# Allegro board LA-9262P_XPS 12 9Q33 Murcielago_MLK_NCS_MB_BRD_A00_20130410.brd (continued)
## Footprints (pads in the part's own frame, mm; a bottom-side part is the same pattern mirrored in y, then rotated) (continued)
KC_FBMA-L11-160808-800LMT_2P
  rect 0.889x1.092 smd: 1(0,0) 2(1.5,0)
KC_FBMA-L11-201209-221LMA30_2P
  rect 0.838x1.397 smd: 1(0,0) 2(1.65,0)
L3GD20TR_LGA16_4X4
  oval 0.406x0.686 smd: 1(0,0) 2(0.65,0) 3(1.3,0) 4(1.95,0) 9(1.95,3.6) 10(1.3,3.6) 11(0.65,3.6) 12(0,3.6)
  oval 0.686x0.406 smd: 5(2.775,0.825) 6(2.775,1.475) 7(2.775,2.125) 8(2.775,2.775) 13(-0.825,2.775) 14(-0.825,2.125) 15(-0.825,1.475) 16(-0.825,0.825)
L_1812-1806
  oval 1.016x3.708 smd: 1(0,0) 2(4.013,0)
LED_27-11-T1D-CP1Q1RY-3C_2P
  rect 0.991x0.991 smd: 1(0,0) 2(1.9,0)
LOTES_APCI0019-P001A01_67P-T
  round 1.092 hole 1.092 unplated: (-0.75,-5.275)
  round 1.6 hole 1.6 unplated: (19.25,-5.275)
  oval 0.305x1.549 smd: 1(0,0) 2(0.25,-7.55) 3(0.5,0) 4(0.75,-7.55) 5(1,0) 6(1.25,-7.55) 7(1.5,0) 8(1.75,-7.55) 9(2,0) 10(2.25,-7.55) 11(2.5,0) 12(2.75,-7.55) 13(3,0) 14(3.25,-7.55) 15(3.5,0) 16(3.75,-7.55) 17(4,0) 18(4.25,-7.55) 19(4.5,0) 20(4.75,-7.55) 21(5,0) 22(5.25,-7.55) 23(5.5,0) 24(7.75,-7.55) 25(8,0) 26(8.25,-7.55) 27(8.5,0) 28(8.75,-7.55) 29(9,0) 30(9.25,-7.55) 31(9.5,0) 32(9.75,-7.55) 33(10,0) 34(10.25,-7.55) 35(10.5,0) 36(10.75,-7.55) 37(11,0) 38(11.25,-7.55) 39(11.5,0) 40(11.75,-7.55) 41(12,0) 42(12.25,-7.55) 43(12.5,0) 44(12.75,-7.55) 45(13,0) 46(13.25,-7.55) 47(13.5,0) 48(13.75,-7.55) 49(14,0) 50(14.25,-7.55) 51(14.5,0) 52(14.75,-7.55) 53(15,0) 54(15.25,-7.55) 55(15.5,0) 56(15.75,-7.55) 57(16,0) 58(16.25,-7.55) 59(16.5,0) 60(16.75,-7.55) 61(17,0) 62(17.25,-7.55) 63(17.5,0) 64(17.75,-7.55) 65(18,0) 66(18.25,-7.55) 67(18.5,0)
  rect 1.194x2.743 smd: 68(-1.1,-0.775) 69(19.6,-0.775)
LPS331APTR_HCLGA16_3X3
  oval 0.305x0.66 smd: 1(0,0) 2(0.5,0) 3(1,0) 4(1.5,0) 5(2,0) 9(2,2.65) 10(1.5,2.65) 11(1,2.65) 12(0.5,2.65) 13(0,2.65)
  oval 0.66x0.305 smd: 6(2.325,0.825) 7(2.325,1.325) 8(2.325,1.825) 14(-0.325,1.825) 15(-0.325,1.325) 16(-0.325,0.825)
LSM303DLHCTR_LGA14_3X5
  oval 0.61x1.092 smd: 1(0,0) 2(0.8,0) 3(1.6,0) 4(2.4,0) 5(3.2,0) 6(4,0) 8(4,2.2) 9(3.2,2.2) 10(2.4,2.2) 11(1.6,2.2) 12(0.8,2.2) 13(0,2.2)
  oval 1.092x0.61 smd: 7(4.1,1.1) 14(-0.1,1.1)
MMBT3904_SOT23-3
  oval 1.016x1.524 smd: 1(0,0) 2(0.965,2.083) 3(-0.965,2.083)
MT41J256M16RE-15E-D_FBGA_96P
  round 0.343 smd: A1(0,0) A2(0.8,0) A3(1.6,0) A7(4.8,0) A8(5.6,0) A9(6.4,0) B1(0,-0.8) B2(0.8,-0.8) B3(1.6,-0.8) B7(4.8,-0.8) B8(5.6,-0.8) B9(6.4,-0.8) C1(0,-1.6) C2(0.8,-1.6) C3(1.6,-1.6) C7(4.8,-1.6) C8(5.6,-1.6) C9(6.4,-1.6) D1(0,-2.4) D2(0.8,-2.4) D3(1.6,-2.4) D7(4.8,-2.4) D8(5.6,-2.4) D9(6.4,-2.4) E1(0,-3.2) E2(0.8,-3.2) E3(1.6,-3.2) E7(4.8,-3.2) E8(5.6,-3.2) E9(6.4,-3.2) F1(0,-4) F2(0.8,-4) F3(1.6,-4) F7(4.8,-4) F8(5.6,-4) F9(6.4,-4) G1(0,-4.8) G2(0.8,-4.8) G3(1.6,-4.8) G7(4.8,-4.8) G8(5.6,-4.8) G9(6.4,-4.8) H1(0,-5.6) H2(0.8,-5.6) H3(1.6,-5.6) H7(4.8,-5.6) H8(5.6,-5.6) H9(6.4,-5.6) J1(0,-6.4) J2(0.8,-6.4) J3(1.6,-6.4) J7(4.8,-6.4) J8(5.6,-6.4) J9(6.4,-6.4) K1(0,-7.2) K2(0.8,-7.2) K3(1.6,-7.2) K7(4.8,-7.2) K8(5.6,-7.2) K9(6.4,-7.2) L1(0,-8) L2(0.8,-8) L3(1.6,-8) L7(4.8,-8) L8(5.6,-8) L9(6.4,-8) M1(0,-8.8) M2(0.8,-8.8) M3(1.6,-8.8) M7(4.8,-8.8) M8(5.6,-8.8) M9(6.4,-8.8) N1(0,-9.6) N2(0.8,-9.6) N3(1.6,-9.6) N7(4.8,-9.6) N8(5.6,-9.6) N9(6.4,-9.6) P1(0,-10.4) P2(0.8,-10.4) P3(1.6,-10.4) P7(4.8,-10.4) P8(5.6,-10.4) P9(6.4,-10.4) R1(0,-11.2) R2(0.8,-11.2) R3(1.6,-11.2) R7(4.8,-11.2) R8(5.6,-11.2) R9(6.4,-11.2) T1(0,-12) T2(0.8,-12) T3(1.6,-12) T7(4.8,-12) T8(5.6,-12) T9(6.4,-12)
MURAT_BLM18BD102SN1D_L0603_2P
  rect 0.66x1.041 smd: 1(0,0) 2(1.2,0)
MURAT_BLM18SG700TN1D_2P
  rect 0.66x1.041 smd: 1(0,0) 2(1.2,0)
MURAT_DLW21SN670HQ2L_4P
  rect 0.889x0.406 smd: 1(0,0) 2(1.7,0) 3(1.7,0.8) 4(0,0.8)
MURAT_LQM2MPN2R2NG0L_2P
  rect 0.787x1.803 smd: 1(0,0) 2(1.6,0)
NC7SZ175P6X_SC70-6
  oval 0.406x0.508 smd: 1(0,0) 2(0.65,0) 3(1.3,0) 4(1.3,1.9) 5(0.65,1.9) 6(0,1.9)
NCP4545IMNTWG_QFN18_3X3
  oval 0.254x0.94 smd: 1(0,0) 2(0.5,0) 3(1,0) 4(1.5,0) 10(1.5,3.05) 11(1,3.05) 12(0.5,3.05) 13(0,3.05)
  oval 0.94x0.254 smd: 5(2.275,0.525) 6(2.275,1.025) 7(2.275,1.525) 8(2.275,2.025) 9(2.275,2.525) 14(-0.775,2.525) 15(-0.775,2.025) 16(-0.775,1.525) 17(-0.775,1.025) 18(-0.775,0.525)
  rect 1.854x1.854 smd: 19(0.75,1.525)
PESD5V0U2BT_SOT23-3
  oval 1.016x1.524 smd: 1(0,0) 2(0.965,2.083) 3(-0.965,2.083)
R0402_0OHM
  rect 0.508x0.559 smd: 1(0,0) 2(0.914,0)
R0603_0OHM
  rect 0.635x0.889 smd: 1(0,0) 2(1.397,0)
R0805_0OHM
  rect 0.813x1.397 smd: 1(0,0) 2(1.702,0)
R_0402
  rect 0.508x0.559 smd: 1(0,0) 2(0.914,0)
R_0603
  rect 0.635x0.889 smd: 1(0,0) 2(1.397,0)
R_0805
  rect 0.813x1.397 smd: 1(0,0) 2(1.702,0)
R_1206
  rect 1.016x1.651 smd: 1(0,0) 2(2.667,0)
R_1206_4P-D
  custom 0.445x0.445 smd: 1(0,0) 4(5.004,0)
  custom 0.114x0.114 smd: 2(1.194,0) 3(3.81,0)
RB751V-40_SOD323-2
  rect 0.787x0.889 smd: 1(0,0) 2(2.14,0)
RB751V-40GTE-17_SOD323-2
  rect 0.787x0.889 smd: 1(0,0) 2(2.1,0)
RB751V-40TE17_SOD323-2
  rect 0.787x0.889 smd: 1(0,0) 2(0,-2.1)
RCLAMP0524PATCT_SLP2510P8-10-9
  oval 0.203x0.686 smd: 1(0,0) 2(0.5,0) 4(1.5,0) 5(2,0) 6(2,0.875) 7(1.5,0.875) 8(0.5,0.875) 9(0,0.875)
  oval 0.406x1.549 smd: 3(1,0.437)
RHU002N06_SOT323-3
  oval 0.813x0.914 smd: 1(0,0) 2(0.65,1.6) 3(-0.65,1.6)
RP_0804_8P4R
  oval 0.66x0.254 smd: 1(0,0) 2(0,-0.5) 3(0,-1) 4(0,-1.5) 5(1.15,-1.5) 6(1.15,-1) 7(1.15,-0.5) 8(1.15,0)
RT8207MZQW_WQFN20_3X3
  oval 0.203x0.889 smd: 1(0,0) 2(0.4,0) 3(0.8,0) 4(1.2,0) 5(1.6,0) 11(1.6,3.1) 12(1.2,3.1) 13(0.8,3.1) 14(0.4,3.1) 15(0,3.1)
  oval 0.889x0.203 smd: 6(2.35,0.75) 7(2.35,1.15) 8(2.35,1.55) 9(2.35,1.95) 10(2.35,2.35) 16(-0.75,2.35) 17(-0.75,1.95) 18(-0.75,1.55) 19(-0.75,1.15) 20(-0.75,0.75)
  rect 1.702x1.702 smd: 21(0.8,1.55)
SAMTE_BSH-030-01-L-D-A_60P
  round 1.016 hole 1.016 unplated: (-2.81,5.53) (17.316,5.53)
  oval 0.279x2.261 smd: 1(0,0) 2(0,5.728) 3(0.5,0) 4(0.5,5.728) 5(1,0) 6(1,5.728) 7(1.5,0) 8(1.5,5.728) 9(2,0) 10(2,5.728) 11(2.5,0) 12(2.5,5.728) 13(3,0) 14(3,5.728) 15(3.5,0) 16(3.5,5.728) 17(4,0) 18(4,5.728) 19(4.5,0) 20(4.5,5.728) 21(5,0) 22(5,5.728) 23(5.5,0) 24(5.5,5.728) 25(6,0) 26(6,5.728) 27(6.5,0) 28(6.5,5.728) 29(7,0) 30(7,5.728) 31(7.5,0) 32(7.5,5.728) 33(8,0) 34(8,5.728) 35(8.5,0) 36(8.5,5.728) 37(9,0) 38(9,5.728) 39(9.5,0) 40(9.5,5.728) 41(10,0) 42(10,5.728) 43(10.5,0) 44(10.5,5.728) 45(11,0) 46(11,5.728) 47(11.5,0) 48(11.5,5.728) 49(12,0) 50(12,5.728) 51(12.5,0) 52(12.5,5.728) 53(13,0) 54(13,5.728) 55(13.5,0) 56(13.5,5.728) 57(14,0) 58(14,5.728) 59(14.5,0) 60(14.5,5.728)
SDMK0340L-7-F_SOD323-2
  rect 1.346x0.66 smd: 1(0,0) 2(2.4,0)
SHARK-BAY-ULT_BGA_1168P-T
  round 0.508 smd: A3(-1.137,0) A62(-38.036,0) AW1(0,22.042) AW63(-38.628,22.057) AY2(-0.543,22.628) AY62(-38.062,22.628) B2(-0.508,0.508) B63(-38.628,0.592) C1(0,1.137)
  round 0.381 smd: A4(-1.894,0) A5(-2.554,0) A6(-3.75,0) A59(-35.9,0) A60(-36.726,0) A61(-37.386,0) AA9(-5.032,11.576) AA21(-11.688,11.489) AA23(-13.115,11.489) AA58(-35.377,11.33) AB10(-5.476,12.053) AB20(-11.18,11.896) AB21(-11.688,12.302) AB22(-12.607,11.896) AB23(-13.115,12.302) AB57(-35.057,11.98) AC9(-5.032,12.529) AC20(-11.18,12.709) AC22(-12.607,12.709) AC58(-35.377,12.63) AD10(-5.476,13.005) AD21(-11.688,13.115) AD23(-13.115,13.115) AD57(-35.057,13.28) AE9(-5.032,13.481) AE10(-5.476,13.958) AE20(-11.18,13.521) AE21(-11.688,13.928) AE22(-12.607,13.521) AE23(-13.115,13.928) AE58(-35.377,13.931) AF9(-5.032,14.434) AF11(-6.059,14.282) AF12(-6.872,14.282) AF14(-7.685,14.282) AF15(-8.497,14.282) AF17(-9.31,14.282) AF18(-10.123,14.282) AF20(-10.936,14.282) AF22(-12.607,14.334) AG10(-5.653,14.79) AG11(-6.465,14.79) AG13(-7.278,14.79) AG14(-8.091,14.79) AG16(-8.904,14.79) AG17(-9.717,14.79) AG19(-10.529,14.79) AG20(-11.342,14.79) AG23(-13.115,14.741) AG57(-35.057,14.581) AG58(-35.692,15.009) AH22(-12.607,15.147) AH24(-13.92,15.289) AH26(-15.22,15.289) AH28(-16.521,15.289) AH30(-17.821,15.289) AH32(-19.122,15.289) AH34(-20.422,15.289) AH36(-21.723,15.289) AH38(-23.023,15.289) AH40(-24.324,15.289) AH42(-25.624,15.289) AH44(-26.925,15.289) AH46(-28.225,15.289) AH49(-29.526,15.289) AH51(-30.826,15.289) AH53(-32.127,15.289) AH55(-33.427,15.289) AH57(-34.728,15.289) AJ23(-13.115,15.553) AJ25(-14.57,15.614) AJ27(-15.871,15.614) AJ29(-17.171,15.614) AJ31(-18.472,15.614) AJ33(-19.772,15.614) AJ35(-21.073,15.614) AJ37(-22.373,15.614) AJ39(-23.674,15.614) AJ41(-24.974,15.614) AJ43(-26.275,15.614) AJ45(-27.575,15.614) AJ47(-28.875,15.614) AJ50(-30.176,15.614) AJ52(-31.476,15.614) AJ54(-32.777,15.614) AJ56(-34.077,15.614) AJ58(-35.378,15.614) AT1(0,19.997) AT63(-38.628,19.848) AU1(0,20.657) AU63(-38.628,20.673) AV1(0,21.318) AV2(-0.66,21.308) AV62(-37.978,21.318) AV63(-38.628,21.333) AW2(-0.66,21.968) AW3(-1.321,21.968) AW61(-37.328,21.978) AW62(-37.978,21.978) AY3(-1.267,22.628) AY4(-1.928,22.628) AY5(-2.588,22.628) AY59(-36.088,22.628) AY60(-36.748,22.628) AY61(-37.409,22.628) B3(-1.259,0.65) B61(-37.315,0.66) B62(-37.978,0.724) C2(-0.65,1.259) C62(-37.978,1.384) C63(-38.628,1.316) D1(0,1.861) D63(-38.628,1.976) E1(0,2.522) E23(-13.333,2.601) E25(-14.714,2.601) E27(-15.84,2.601) E29(-17.221,2.601) E31(-18.348,2.601) E33(-19.729,2.601) E35(-20.855,2.601) E37(-22.236,2.601) E39(-23.363,2.601) E41(-24.744,2.601) E43(-25.87,2.601) E45(-27.251,2.601) E47(-28.378,2.601) E49(-29.759,2.601) E51(-30.885,2.601) E53(-32.266,2.601) E55(-33.393,2.601) E57(-34.774,2.601) E63(-38.628,2.647) F1(0,3.436) F22(-12.717,3.058) F24(-14.023,3.126) F26(-15.277,3.126) F28(-16.531,3.126) F30(-17.785,3.126) F32(-19.038,3.126) F34(-20.292,3.126) F36(-21.546,3.126) F38(-22.8,3.126) F40(-24.053,3.126) F42(-25.307,3.126) F44(-26.561,3.126) F46(-27.815,3.126) F48(-29.068,3.126) F50(-30.322,3.126) F52(-31.576,3.126) F54(-32.83,3.126) F56(-34.083,3.126) F58(-35.377,3.126) G22(-12.607,3.768) G23(-13.333,3.451) G25(-14.714,3.451) G27(-15.84,3.451) G29(-17.221,3.451) G31(-18.348,3.451) G33(-19.729,3.451) G35(-20.855,3.451) G37(-22.236,3.451) G39(-23.363,3.451) G41(-24.744,3.451) G43(-25.87,3.451) G45(-27.251,3.451) G47(-28.378,3.451) G49(-29.759,3.451) G51(-30.885,3.451) G53(-32.266,3.451) G55(-33.393,3.451) G57(-34.774,3.451) H22(-12.607,4.581) H23(-13.115,4.174) H57(-35.057,4.101) J22(-12.607,5.393) J23(-13.115,4.987) J58(-35.377,4.827) K9(-5.032,5.861) K10(-5.935,5.7) K12(-6.888,5.7) K14(-7.84,5.7) K16(-8.793,5.7) K18(-9.745,5.7) K19(-10.698,5.7) K21(-11.65,5.7) K23(-13.115,5.8) K57(-35.057,5.478) L10(-5.476,6.338) L11(-6.412,6.144) L13(-7.364,6.144) L15(-8.317,6.144) L17(-9.269,6.144) L18(-10.222,6.144) L20(-11.18,6.206) L22(-12.607,6.206) L58(-35.377,6.128) M9(-5.032,6.814) M20(-11.18,7.019) M21(-11.688,6.613) M22(-12.607,7.019) M23(-13.115,6.613) M57(-35.057,6.778) N10(-5.476,7.29) N21(-11.688,7.425) N23(-13.115,7.425) N58(-35.377,7.428) P9(-5.032,7.766) P20(-11.18,7.832) P22(-12.607,7.832) P57(-35.057,8.078) R10(-5.476,8.243) R20(-11.18,8.645) R21(-11.688,8.238) R22(-12.607,8.645) R23(-13.115,8.238) T9(-5.032,8.719) T21(-11.688,9.051) T23(-13.115,9.051) T58(-35.377,8.729) U9(-5.032,9.671) U10(-5.476,9.195) U20(-11.18,9.457) U22(-12.607,9.457) U57(-35.057,9.379) V10(-5.476,10.148) V21(-11.688,9.864) V23(-13.115,9.864) V58(-35.377,10.029) W9(-5.032,10.624) W20(-11.18,10.27) W21(-11.688,10.677) W22(-12.607,10.27) W23(-13.115,10.677) W57(-35.057,10.679) Y10(-5.476,11.1) Y20(-11.18,11.083) Y22(-12.607,11.083)
  round 0.305 smd: A8(-4.538,0) A9(-5.452,0) A11(-6.367,0) A12(-7.116,0) A14(-8.03,0) A15(-8.945,0) A17(-9.694,0) A18(-10.608,0) A20(-11.523,0) A21(-12.272,0) A23(-13.186,0) A24(-14.023,0.325) A25(-14.714,0) A27(-15.84,0) A28(-16.531,0.325) A29(-17.221,0) A31(-18.348,0) A32(-19.038,0.325) A33(-19.729,0) A35(-20.855,0) A36(-21.546,0.325) A37(-22.236,0) A39(-23.363,0) A40(-24.053,0.325) A41(-24.744,0) A43(-25.87,0) A44(-26.561,0.325) A45(-27.251,0) A47(-28.378,0) A48(-29.068,0.325) A49(-29.759,0) A51(-30.885,0) A52(-31.576,0.325) A53(-32.266,0) A55(-33.393,0) A56(-34.083,0.325) A57(-34.774,0) AA1(0,11.717) AA2(-0.65,11.717) AA3(-1.3,11.678) AA4(-1.951,11.678) AA59(-36.027,11.638) AA60(-36.678,11.638) AA61(-37.328,11.638) AA62(-37.978,11.676) AA63(-38.628,11.676) AB5(-2.637,12.053) AB6(-3.287,12.053) AB7(-3.937,12.053) AB8(-4.587,12.053) AC1(0,12.466) AC2(-0.65,12.466) AC3(-1.3,12.504) AC4(-1.951,12.504) AC59(-36.027,12.464) AC60(-36.678,12.464) AC61(-37.328,12.464) AC62(-37.978,12.426) AC63(-38.628,12.426) AD1(0,13.215) AD2(-0.65,13.215) AD3(-1.3,13.177) AD4(-1.951,13.177) AD5(-2.637,13.005) AD6(-3.287,13.005) AD7(-3.937,13.005) AD8(-4.587,13.005) AD59(-36.027,13.137) AD60(-36.678,13.137) AD61(-37.328,13.137) AD62(-37.978,13.175) AD63(-38.628,13.175) AE5(-2.637,13.958) AE6(-3.287,13.958) AE7(-3.937,13.958) AE8(-4.587,13.958) AE59(-36.027,13.962) AE60(-36.678,13.962) AE61(-37.328,13.962) AE62(-37.978,13.924) AE63(-38.628,13.924) AF1(0,13.964) AF2(-0.65,13.964) AF3(-1.3,14.003) AF4(-1.951,14.003) AG1(0,14.714) AG2(-0.65,14.714) AG3(-1.3,14.676) AG4(-1.951,14.676) AG5(-2.637,14.91) AG6(-3.287,14.91) AG7(-3.937,14.91) AG8(-4.587,14.91) AG21(-11.955,15.122) AG60(-36.352,14.602) AG61(-37.003,14.602) AG62(-37.653,14.602) AG63(-38.303,14.602) AH1(0,15.463) AH2(-0.65,15.463) AH3(-1.3,15.501) AH4(-1.951,15.501) AH10(-5.653,15.476) AH11(-6.465,15.476) AH13(-7.278,15.476) AH14(-8.091,15.476) AH16(-8.904,15.476) AH17(-9.717,15.476) AH19(-10.529,15.476) AH20(-11.342,15.476) AH60(-36.678,15.278) AH61(-37.328,15.278) AH62(-37.978,15.278) AH63(-38.628,15.278) AJ5(-2.637,15.863) AJ6(-3.287,15.863) AJ7(-3.937,15.863) AJ8(-4.587,15.863) AJ10(-5.653,16.126) AJ11(-6.465,16.126) AJ13(-7.278,16.126) AJ14(-8.091,16.126) AJ60(-36.352,15.954) AJ61(-37.003,15.954) AJ62(-37.653,15.954) AJ63(-38.303,15.954) AK1(0,16.212) AK2(-0.65,16.212) AK3(-1.3,16.174) AK4(-1.951,16.174) AK8(-4.303,16.451) AK18(-9.848,16.266) AK20(-10.801,16.266) AK21(-11.753,16.266) AK60(-36.678,16.523) AK61(-37.328,16.523) AK62(-37.978,16.629) AK63(-38.628,16.629) AL1(0,16.962) AL2(-0.65,16.962) AL3(-1.3,17) AL4(-1.951,17) AL5(-2.901,16.776) AL7(-3.739,16.776) AL8(-4.303,17.101) AL10(-5.658,16.776) AL11(-6.221,17.101) AL13(-7.576,16.776) AL15(-8.14,17.101) AL17(-9.222,16.583) AL18(-9.848,16.916) AL20(-10.801,16.916) AL21(-11.753,16.916) AL22(-12.706,16.916) AL23(-13.529,16.916) AL25(-14.504,16.916) AL26(-15.456,16.916) AL28(-16.409,16.916) AL29(-17.361,16.916) AL31(-18.26,16.591) AL32(-18.824,16.916) AL33(-19.726,16.916) AL35(-20.729,16.916) AL36(-21.58,16.916) AL38(-22.634,16.916) AL39(-23.542,16.591) AL40(-24.131,16.916) AL42(-24.944,16.916) AL43(-25.897,16.916) AL45(-26.874,16.916) AL46(-27.802,16.916) AL48(-28.856,16.916) AL49(-29.757,16.916) AL51(-30.761,16.916) AL52(-31.583,16.916) AL54(-32.61,16.916) AL55(-33.562,16.916) AL57(-34.509,16.916) AL58(-35.408,16.916) AL60(-36.352,17.169) AL61(-37.003,17.169) AM1(0,17.711) AM2(-0.65,17.711) AM3(-1.3,17.673) AM4(-1.951,17.673) AM5(-2.901,17.426) AM7(-3.739,17.426) AM8(-4.303,17.752) AM10(-5.658,17.426) AM11(-6.221,17.752) AM13(-7.576,17.426) AM15(-8.14,17.752) AM17(-9.222,17.233) AM18(-9.848,17.567) AM20(-10.801,17.567) AM21(-11.753,17.567) AM22(-12.706,17.567) AM23(-13.529,17.567) AM25(-14.504,17.567) AM26(-15.456,17.567) AM28(-16.409,17.567) AM29(-17.361,17.567) AM31(-18.26,17.242) AM32(-18.824,17.567) AM33(-19.726,17.567) AM35(-20.729,17.567) AM36(-21.58,17.567) AM38(-22.634,17.567) AM40(-24.131,17.567) AM42(-24.944,17.567) AM43(-25.897,17.567) AM45(-26.874,17.567) AM46(-27.802,17.567) AM48(-28.856,17.567) AM49(-29.757,17.567) AM51(-30.761,17.567) AM52(-31.583,17.567) AM54(-32.61,17.567) AM55(-33.562,17.567) AM57(-34.509,17.567) AM58(-35.408,17.567) AM60(-36.678,17.816) AM61(-37.328,17.816) AM62(-37.978,17.709) AM63(-38.628,17.709) AN1(0,18.46) AN2(-0.65,18.46) AN3(-1.3,18.498) AN4(-1.951,18.498) AN5(-2.901,18.077) AN7(-3.739,18.077) AN8(-4.303,18.402) AN10(-5.658,18.077) AN11(-6.221,18.402) AN13(-7.576,18.077) AN15(-8.14,18.402) AN17(-9.222,17.883) AN18(-9.848,18.217) AN20(-10.801,18.217) AN21(-11.753,18.217) AN22(-12.706,18.217) AN23(-13.529,18.217) AN25(-14.504,18.217) AN26(-15.456,18.217) AN28(-16.409,18.217) AN29(-17.361,18.217) AN31(-18.26,17.892) AN32(-18.824,18.217) AN33(-19.726,18.217) AN35(-20.729,18.217) AN36(-21.58,18.217) AN38(-22.634,18.217) AN39(-23.542,17.892) AN40(-24.131,18.217) AN42(-24.944,18.217) AN43(-25.897,18.217) AN45(-26.874,18.217) AN46(-27.802,18.217) AN48(-28.856,18.217) AN49(-29.757,18.217) AN51(-30.761,18.217) AN52(-31.583,18.217) AN54(-32.61,18.217) AN55(-33.562,18.217) AN57(-34.509,18.217) AN58(-35.408,18.217) AN60(-36.352,18.385) AN61(-37.003,18.385) AN62(-37.653,18.385) AN63(-38.303,18.385) AP1(0,19.21) AP2(-0.65,19.21) AP3(-1.3,19.171) AP4(-1.951,19.171) AP5(-2.901,18.727) AP7(-3.739,18.727) AP8(-4.303,19.052) AP10(-5.658,18.727) AP11(-6.221,19.052) AP13(-7.576,18.727) AP15(-8.14,19.052) AP17(-9.222,18.533) AP18(-9.848,18.867) AP20(-10.801,18.867) AP21(-11.753,18.867) AP22(-12.706,18.867) AP23(-13.529,18.867) AP25(-14.504,18.867) AP26(-15.456,18.867) AP28(-16.409,18.867) AP29(-17.361,18.867) AP31(-18.26,18.542) AP32(-18.824,18.867) AP33(-19.726,18.867) AP35(-20.729,18.867) AP36(-21.58,18.867) AP38(-22.634,18.867) AP39(-23.542,18.542) AP40(-24.131,18.867) AP42(-24.944,18.867) AP43(-25.897,18.867) AP45(-26.874,18.867) AP46(-27.802,18.867) AP48(-28.856,18.867) AP49(-29.757,18.867) AP51(-30.761,18.867) AP52(-31.583,18.867) AP54(-32.61,18.867) AP55(-33.562,18.867) AP57(-34.509,18.867) AP58(-35.408,18.867) AP60(-36.678,19.06) AP61(-37.328,19.06) AP62(-37.978,19.06) AP63(-38.628,19.06) AR5(-2.901,19.377) AR7(-3.739,19.377) AR8(-4.303,19.702) AR10(-5.658,19.377) AR11(-6.221,19.702) AR13(-7.576,19.377) AR15(-8.14,19.702) AR17(-9.222,19.184) AR18(-9.848,19.517) AR20(-10.801,19.517) AR21(-11.753,19.517) AR22(-12.706,19.517) AR23(-13.529,19.517) AR25(-14.504,19.517) AR26(-15.456,19.517) AR28(-16.409,19.517) AR29(-17.361,19.517) AR31(-18.26,19.192) AR32(-18.824,19.517) AR33(-19.726,19.517) AR35(-20.729,19.517) AR36(-21.58,19.517) AR38(-22.634,19.517) AR39(-23.542,19.192) AR40(-24.131,19.517) AR42(-24.944,19.517) AR43(-25.897,19.517) AR45(-26.874,19.517) AR46(-27.802,19.517) AR48(-28.856,19.517) AR49(-29.757,19.517) AR51(-30.761,19.517) AR52(-31.583,19.517) AR54(-32.61,19.517) AR55(-33.562,19.517) AR57(-34.509,19.517) AR58(-35.408,19.517) AT2(-0.65,19.959) AT3(-1.3,19.997) AT4(-1.951,19.997) AT5(-2.901,20.027) AT7(-3.739,20.027) AT10(-5.658,20.027) AT13(-7.576,20.027) AT35(-20.437,20.22) AT37(-22.011,20.22) AT40(-23.586,20.22) AT42(-25.161,20.22) AT43(-26.736,20.22) AT46(-28.311,20.22) AT49(-29.912,20.248) AT61(-37.003,19.634) AT62(-37.812,19.69) AU2(-0.655,20.647) AU3(-1.315,20.647) AU4(-1.976,20.647) AU6(-3.337,20.678) AU7(-4.163,20.678) AU8(-4.836,20.678) AU10(-5.661,20.678) AU11(-6.335,20.678) AU12(-7.16,20.678) AU14(-7.833,20.678) AU15(-8.659,20.678) AU16(-9.222,20.353) AU17(-9.86,20.678) AU18(-10.536,20.353) AU19(-11.105,20.678) AU20(-11.751,20.353) AU21(-12.397,20.678) AU22(-12.966,20.353) AU23(-13.642,20.678) AU24(-14.318,20.353) AU25(-14.993,20.678) AU26(-15.669,20.353) AU27(-16.238,20.678) AU28(-16.884,20.353) AU29(-17.531,20.678) AU30(-18.1,20.353) AU31(-18.775,20.678) AU33(-19.372,20.33) AU34(-19.974,20.678) AU35(-20.899,20.678) AU36(-21.549,20.678) AU37(-22.474,20.678) AU39(-23.124,20.678) AU40(-24.048,20.678) AU41(-24.699,20.678) AU42(-25.623,20.678) AU43(-26.274,20.678) AU44(-27.198,20.678) AU46(-27.848,20.678) AU47(-28.773,20.678) AU49(-29.423,20.678) AU50(-30.4,20.678) AU51(-30.98,20.353) AU52(-31.656,20.678) AU53(-32.331,20.353) AU54(-32.9,20.678) AU55(-33.547,20.353) AU56(-34.193,20.678) AU57(-34.762,20.353) AU58(-35.438,20.678) AU59(-36.002,20.353) AU60(-36.566,20.678) AU61(-37.277,20.401) AU62(-37.978,20.663) AV3(-1.321,21.308) AV4(-1.976,21.308) AV5(-2.664,21.328) AV6(-3.337,21.328) AV7(-4.163,21.328) AV8(-4.836,21.328) AV10(-5.661,21.328) AV11(-6.335,21.328) AV12(-7.16,21.328) AV14(-7.833,21.328) AV15(-8.659,21.328) AV16(-9.222,21.003) AV17(-9.86,21.328) AV18(-10.536,21.003) AV19(-11.105,21.328) AV20(-11.751,21.003) AV21(-12.397,21.328) AV22(-12.966,21.003) AV23(-13.642,21.328) AV24(-14.318,21.003) AV25(-14.993,21.328) AV26(-15.669,21.003) AV27(-16.238,21.328) AV28(-16.884,21.003) AV29(-17.531,21.328) AV30(-18.1,21.003) AV31(-18.775,21.328) AV33(-19.4,21.003) AV34(-20.024,21.328) AV35(-20.849,21.328) AV36(-21.599,21.328) AV37(-22.424,21.328) AV39(-23.173,21.328) AV40(-23.999,21.328) AV41(-24.748,21.328) AV42(-25.574,21.328) AV43(-26.323,21.328) AV44(-27.149,21.328) AV46(-27.898,21.328) AV47(-28.723,21.328) AV49(-29.473,21.328) AV50(-30.298,21.328) AV51(-30.98,21.003) AV52(-31.656,21.328) AV53(-32.331,21.003) AV54(-32.9,21.328) AV55(-33.547,21.003) AV56(-34.193,21.328) AV57(-34.762,21.003) AV58(-35.438,21.328) AV59(-36.002,21.003) AV60(-36.566,21.328) AV61(-37.302,21.051) AW4(-1.976,21.968) AW5(-2.626,21.978) AW6(-3.375,21.978) AW7(-4.125,21.978) AW8(-4.874,21.978) AW10(-5.623,21.978) AW11(-6.373,21.978) AW12(-7.122,21.978) AW14(-7.871,21.978) AW15(-8.621,21.978) AW16(-9.222,21.653) AW17(-9.86,21.978) AW18(-10.536,21.653) AW19(-11.211,21.978) AW21(-12.291,21.978) AW22(-12.966,21.653) AW23(-13.642,21.978) AW24(-14.318,21.653) AW25(-14.993,21.978) AW26(-15.669,21.653) AW27(-16.345,21.978) AW29(-17.424,21.978) AW30(-18.1,21.653) AW31(-18.775,21.978) AW33(-19.451,21.653) AW34(-20.024,21.978) AW35(-20.849,21.978) AW36(-21.599,21.978) AW37(-22.424,21.978) AW39(-23.173,21.978) AW40(-23.999,21.978) AW41(-24.748,21.978) AW42(-25.574,21.978) AW43(-26.323,21.978) AW44(-27.149,21.978) AW46(-27.898,21.978) AW47(-28.723,21.978) AW49(-29.473,21.978) AW50(-30.298,21.978) AW51(-30.98,21.653) AW52(-31.656,21.978) AW53(-32.331,21.653) AW54(-33.007,21.978) AW56(-34.087,21.978) AW57(-34.762,21.653) AW58(-35.438,21.978) AW59(-36.002,21.653) AW60(-36.566,21.978) AY6(-3.375,22.628) AY7(-4.125,22.628) AY8(-4.874,22.628) AY10(-5.623,22.628) AY11(-6.373,22.628) AY12(-7.122,22.628) AY14(-7.871,22.628) AY15(-8.621,22.628) AY16(-9.184,22.303) AY17(-9.86,22.628) AY18(-10.536,22.303) AY19(-11.211,22.628) AY21(-12.291,22.628) AY22(-12.966,22.303) AY23(-13.642,22.628) AY24(-14.318,22.303) AY25(-14.993,22.628) AY26(-15.669,22.303) AY27(-16.345,22.628) AY29(-17.424,22.628) AY30(-18.1,22.303) AY31(-18.775,22.628) AY33(-19.451,22.303) AY34(-20.024,22.628) AY35(-20.849,22.628) AY36(-21.599,22.628) AY37(-22.424,22.628) AY39(-23.173,22.628) AY40(-23.999,22.628) AY41(-24.748,22.628) AY42(-25.574,22.628) AY43(-26.323,22.628) AY44(-27.149,22.628) AY46(-27.898,22.628) AY47(-28.723,22.628) AY49(-29.473,22.628) AY50(-30.298,22.628) AY51(-30.98,22.303) AY52(-31.656,22.628) AY53(-32.331,22.303) AY54(-33.007,22.628) AY56(-34.087,22.628) AY57(-34.762,22.303) AY58(-35.438,22.628) B4(-1.922,0.65) B5(-3.138,0.643) B6(-4.119,0.643) B8(-4.891,0.643) B9(-5.716,0.643) B11(-6.697,0.643) B12(-7.469,0.643) B14(-8.294,0.643) B15(-9.275,0.643) B17(-10.047,0.643) B18(-10.872,0.643) B20(-11.853,0.643) B21(-12.272,1.196) B22(-12.625,0.643) B23(-13.451,0.643) B24(-14.023,0.975) B25(-14.714,0.65) B26(-15.277,0.975) B27(-15.84,0.65) B28(-16.531,0.975) B29(-17.221,0.65) B30(-17.785,0.975) B31(-18.348,0.65) B32(-19.038,0.975) B33(-19.729,0.65) B34(-20.292,0.975) B35(-20.855,0.65) B36(-21.546,0.975) B37(-22.236,0.65) B38(-22.8,0.975) B39(-23.363,0.65) B40(-24.053,0.975) B41(-24.744,0.65) B42(-25.307,0.975) B43(-25.87,0.65) B44(-26.561,0.975) B45(-27.251,0.65) B46(-27.815,0.975) B47(-28.378,0.65) B48(-29.068,0.975) B49(-29.759,0.65) B50(-30.322,0.975) B51(-30.885,0.65) B52(-31.576,0.975) B53(-32.266,0.65) B54(-32.83,0.975) B55(-33.393,0.65) B56(-34.083,0.975) B57(-34.774,0.65) B58(-35.337,0.975) B59(-35.9,0.65) B60(-36.665,0.66) C3(-1.302,1.302) C4(-2.118,1.272) C5(-2.772,1.196) C6(-3.776,1.196) C8(-4.538,1.196) C9(-5.351,1.196) C11(-6.354,1.196) C12(-7.116,1.196) C14(-7.929,1.196) C15(-8.932,1.196) C17(-9.694,1.196) C18(-10.507,1.196) C20(-11.51,1.196) C21(-11.891,1.786) C22(-12.678,1.786) C23(-13.085,1.196) C24(-14.051,2.032) C25(-14.714,1.3) C26(-15.277,1.626) C27(-15.84,1.3) C28(-16.558,2.032) C29(-17.221,1.3) C30(-17.785,1.626) C31(-18.348,1.3) C32(-19.066,2.032) C33(-19.729,1.3) C34(-20.292,1.626) C35(-20.855,1.3) C36(-21.573,2.032) C37(-22.236,1.3) C38(-22.8,1.626) C39(-23.363,1.3) C40(-24.081,2.032) C41(-24.744,1.3) C42(-25.307,1.626) C43(-25.87,1.3) C44(-26.588,2.032) C45(-27.251,1.3) C46(-27.815,1.626) C47(-28.378,1.3) C48(-29.07,2.032) C49(-29.759,1.3) C50(-30.322,1.626) C51(-30.885,1.3) C52(-31.578,1.991) C53(-32.266,1.3) C54(-32.83,1.626) C55(-33.393,1.3) C56(-34.085,1.991) C57(-34.774,1.3) C58(-35.337,1.626) C59(-35.9,1.3) C61(-37.003,1.237) D2(-0.65,2.075) D3(-1.3,2.037) D5(-2.678,1.842) D6(-3.369,1.786) D8(-4.157,1.786) D9(-4.944,1.786) D11(-5.852,1.786) D12(-6.735,1.786) D14(-7.522,1.786) D15(-8.43,1.786) D17(-9.313,1.786) D18(-10.1,1.786) D20(-11.008,1.786) D21(-12.235,2.423) D23(-13.377,1.786) D25(-14.714,1.951) D26(-15.277,2.276) D27(-15.84,1.951) D29(-17.221,1.951) D30(-17.785,2.276) D31(-18.348,1.951) D33(-19.729,1.951) D34(-20.292,2.276) D35(-20.855,1.951) D37(-22.236,1.951) D38(-22.8,2.276) D39(-23.363,1.951) D41(-24.744,1.951) D42(-25.307,2.276) D43(-25.87,1.951) D45(-27.251,1.951) D46(-27.815,2.276) D47(-28.378,1.951) D49(-29.759,1.951) D50(-30.322,2.276) D51(-30.885,1.951) D53(-32.266,1.951) D54(-32.83,2.276) D55(-33.393,1.951) D57(-34.774,1.951) D58(-35.337,2.276) D59(-35.9,1.951) D60(-36.678,1.801) D61(-37.328,1.801) D62(-37.978,2.035) E2(-0.65,2.725) E3(-1.3,2.687) E4(-1.951,2.687) E5(-2.602,2.619) E6(-3.554,2.619) E8(-4.507,2.619) E10(-5.459,2.619) E11(-6.412,2.619) E13(-7.364,2.619) E15(-8.317,2.619) E17(-9.269,2.619) E18(-10.222,2.619) E20(-11.174,2.619) E59(-36.027,2.647) E60(-36.678,2.647) E61(-37.328,2.647) E62(-37.978,2.685) F2(-0.65,3.474) F3(-1.3,3.512) F4(-1.951,3.512) F5(-2.602,3.269) F6(-3.554,3.269) F8(-4.507,3.269) F10(-5.459,3.269) F11(-6.412,3.269) F13(-7.364,3.269) F15(-8.317,3.269) F17(-9.269,3.269) F18(-10.222,3.269) F20(-11.174,3.269) F59(-36.027,3.472) F60(-36.678,3.472) F61(-37.328,3.472) F62(-37.978,3.434) F63(-38.628,3.434) G1(0,4.224) G2(-0.65,4.224) G3(-1.3,4.185) G4(-1.951,4.185) G5(-2.602,3.919) G6(-3.554,3.919) G8(-4.507,3.919) G10(-5.459,3.919) G11(-6.412,3.919) G13(-7.364,3.919) G15(-8.317,3.919) G17(-9.269,3.919) G18(-10.222,3.919) G20(-11.174,3.919) H5(-2.602,4.569) H6(-3.554,4.569) H8(-4.507,4.569) H10(-5.459,4.569) H11(-6.412,4.569) H13(-7.364,4.569) H15(-8.317,4.569) H17(-9.269,4.569) H18(-10.222,4.569) H20(-11.174,4.569) H59(-36.027,4.145) H60(-36.678,4.145) H61(-37.328,4.145) H62(-37.978,4.183) H63(-38.628,4.183) J1(0,4.973) J2(-0.65,4.973) J3(-1.3,5.011) J4(-1.951,5.011) J5(-2.627,5.22) J6(-3.567,5.22) J8(-4.507,5.22) J10(-5.459,5.22) J11(-6.412,5.22) J13(-7.364,5.22) J15(-8.317,5.22) J17(-9.269,5.22) J18(-10.222,5.22) J20(-11.174,5.22) J21(-12.095,4.986) J59(-36.027,4.971) J60(-36.678,4.971) J61(-37.328,4.971) J62(-37.978,4.933) J63(-38.628,4.933) K1(0,5.722) K2(-0.65,5.722) K3(-1.3,5.684) K4(-1.951,5.684) K59(-36.027,5.644) K60(-36.678,5.644) K61(-37.328,5.644) K62(-37.978,5.682) K63(-38.628,5.682) L1(0,6.471) L2(-0.65,6.471) L3(-1.3,6.51) L4(-1.951,6.51) L5(-2.637,6.338) L6(-3.287,6.338) L7(-3.937,6.338) L8(-4.587,6.338) L59(-36.027,6.469) L60(-36.678,6.469) L61(-37.328,6.469) L62(-37.978,6.431) L63(-38.628,6.431) N1(0,7.221) N2(-0.65,7.221) N3(-1.3,7.183) N4(-1.951,7.183) N5(-2.637,7.29) N6(-3.287,7.29) N7(-3.937,7.29) N8(-4.587,7.29) N59(-36.027,7.142) N60(-36.678,7.142) N61(-37.328,7.142) N62(-37.978,7.181) N63(-38.628,7.181) P1(0,7.97) P2(-0.65,7.97) P3(-1.3,8.008) P4(-1.951,8.008) P59(-36.027,7.968) P60(-36.678,7.968) P61(-37.328,7.968) P62(-37.978,7.93) P63(-38.628,7.93) R5(-2.637,8.243) R6(-3.287,8.243) R7(-3.937,8.243) R8(-4.587,8.243) T1(0,8.719) T2(-0.65,8.719) T3(-1.3,8.681) T4(-1.951,8.681) T59(-36.027,8.641) T60(-36.678,8.641) T61(-37.328,8.641) T62(-37.978,8.679) T63(-38.628,8.679) U1(0,9.469) U2(-0.65,9.469) U3(-1.3,9.507) U4(-1.951,9.507) U5(-2.637,9.195) U6(-3.287,9.195) U7(-3.937,9.195) U8(-4.587,9.195) U59(-36.027,9.467) U60(-36.678,9.467) U61(-37.328,9.467) U62(-37.978,9.428) U63(-38.628,9.428) V1(0,10.218) V2(-0.65,10.218) V3(-1.3,10.18) V4(-1.951,10.18) V5(-2.637,10.148) V6(-3.287,10.148) V7(-3.937,10.148) V8(-4.587,10.148) V59(-36.027,10.14) V60(-36.678,10.14) V61(-37.328,10.14) V62(-37.978,10.178) V63(-38.628,10.178) Y1(0,10.967) Y2(-0.65,10.967) Y3(-1.3,11.005) Y4(-1.951,11.005) Y5(-2.637,11.1) Y6(-3.287,11.1) Y7(-3.937,11.1) Y8(-4.587,11.1) Y59(-36.027,10.965) Y60(-36.678,10.965) Y61(-37.328,10.965) Y62(-37.978,10.927) Y63(-38.628,10.927)
  round 0.33 smd: AK22(-12.655,16.266) AK23(-13.529,16.266) AK25(-14.504,16.266) AK26(-15.456,16.266) AK28(-16.409,16.266) AK29(-17.311,16.266) AK32(-18.824,16.266) AK33(-19.726,16.266) AK35(-20.729,16.266) AK36(-21.58,16.266) AK38(-22.609,16.266) AK40(-24.106,16.266) AK42(-24.944,16.266) AK43(-25.897,16.266) AK45(-26.874,16.266) AK46(-27.776,16.266) AK48(-28.83,16.266) AK49(-29.732,16.266) AK51(-30.735,16.266) AK52(-31.583,16.266) AK54(-32.61,16.266) AK55(-33.562,16.266) AK57(-34.509,16.266) AK58(-35.408,16.266)
SHORTPADS
  custom 0.19x0.19 smd: 1(-0.483,0) 2(0.483,0)
SI1553CDL-T1-GE3_SC70-6
  oval 0.406x0.66 smd: 1(0,0) 2(0.65,0) 3(1.3,0) 4(1.3,1.791) 5(0.65,1.791) 6(0,1.791)
SI3457BDV-T1-E3_TSOP6
  oval 0.508x1.448 smd: 1(0,0) 2(1,0) 3(2,0) 4(2,2.425) 5(1,2.425) 6(0,2.425)
SI7716ADN-T1-GE3_POWERPAK8-5
  oval 0.406x0.991 smd: 1(0,0) 2(0.66,0) 3(1.32,0) 4(1.98,0)
  custom 0.559x0.559 smd: 5(0.99,2.247)
SIR472DP-T1-GE3_POWERPAK8-5
  oval 0.61x1.27 smd: 1(0,0) 2(1.27,0) 3(2.54,0) 4(3.81,0)
  custom 1.105x1.105 smd: 5(1.905,3.36)
SIS412DN-T1-GE3_POWERPAK8-5
  oval 0.406x0.991 smd: 1(0,0) 2(0.66,0) 3(1.32,0) 4(1.98,0)
  custom 0.559x0.559 smd: 5(0.99,2.247)
SN74AHC1G04DCKR_SOT23-5
  oval 0.356x1.219 smd: 1(0,0) 2(0.65,0) 3(1.3,0) 4(1.3,1.675) 5(0,1.675)
SN74AHC1G08DCKR_SC70-5
  oval 0.381x1.295 smd: 1(0,0.15) 2(0.65,0.15) 3(1.3,0.15) 4(1.3,1.89) 5(0,1.89)
SN74AHC1G32DCKR_SC70-5
  oval 0.457x0.711 smd: 1(0,0) 2(0.65,0) 3(1.3,0) 4(1.3,1.85) 5(0,1.85)
SN74CBT1G125DCKR_SC70-5
  oval 0.381x0.864 smd: 1(0,0) 2(0.65,0) 3(1.3,0) 4(1.3,1.74) 5(0,1.74)
SN74CBT3257CPWR_TSSOP16
  oval 0.381x1.651 smd: 1(0,0) 2(0.65,0) 3(1.3,0) 4(1.95,0) 5(2.6,0) 6(3.25,0) 7(3.9,0) 8(4.55,0) 9(4.55,5.775) 10(3.9,5.775) 11(3.25,5.775) 12(2.6,5.775) 13(1.95,5.775) 14(1.3,5.775) 15(0.65,5.775) 16(0,5.775)
SN74LVC1G06DCKR_SC70-5
  oval 0.381x0.864 smd: 1(0,0) 2(0.65,0) 3(1.3,0) 4(1.3,1.74) 5(0,1.74)
SSM3K7002FU_SC70-3
  oval 0.508x0.991 smd: 1(0,0) 2(0.65,1.9) 3(-0.65,1.9)
STM32F103RDY6TR_WLCSP_64P
  round 0.254 smd: A1(0,0) A2(0.5,0) A3(1,0) A4(1.5,0) A5(2,0) A6(2.5,0) A7(3,0) A8(3.5,0) B1(0,-0.5) B2(0.5,-0.5) B3(1,-0.5) B4(1.5,-0.5) B5(2,-0.5) B6(2.5,-0.5) B7(3,-0.5) B8(3.5,-0.5) C1(0,-1) C2(0.5,-1) C3(1,-1) C4(1.5,-1) C5(2,-1) C6(2.5,-1) C7(3,-1) C8(3.5,-1) D1(0,-1.5) D2(0.5,-1.5) D3(1,-1.5) D4(1.5,-1.5) D5(2,-1.5) D6(2.5,-1.5) D7(3,-1.5) D8(3.5,-1.5) E1(0,-2) E2(0.5,-2) E3(1,-2) E4(1.5,-2) E5(2,-2) E6(2.5,-2) E7(3,-2) E8(3.5,-2) F1(0,-2.5) F2(0.5,-2.5) F3(1,-2.5) F4(1.5,-2.5) F5(2,-2.5) F6(2.5,-2.5) F7(3,-2.5) F8(3.5,-2.5) G1(0,-3) G2(0.5,-3) G3(1,-3) G4(1.5,-3) G5(2,-3) G6(2.5,-3) G7(3,-3) G8(3.5,-3) H1(0,-3.5) H2(0.5,-3.5) H3(1,-3.5) H4(1.5,-3.5) H5(2,-3.5) H6(2.5,-3.5) H7(3,-3.5) H8(3.5,-3.5)
SW_EVQP3S01K_4P
  rect 1.651x1.041 smd: 1(0,0) 3(3.85,0)
  rect 1.651x1.041 hole 0.66: 2(-0.1,1.525) 4(3.95,1.525)
SW_SKQGCBE010_4P
  rect 1.803x1.092 smd: 1(0,0) 2(6.2,0) 3(0,-3.7) 4(6.2,-3.7)
SW_WCM2012F2S_4P
  rect 0.889x0.406 smd: 1(0,0) 2(1.7,0) 3(1.7,-0.8) 4(0,-0.8)
TAIWI_USB014-107CRL-TW_10P-T
  round 1.321 hole 0.914: 1(0,0) 2(-2.5,0) 3(-4.5,0) 4(-7,0) 6(-5.75,-1.5) 7(-3.5,-1.5) 8(-1.25,-1.5) 9(1,-1.5)
  round 1.168 hole 0.914: 5(-8,-1.5)
  round 1.016 hole 0.762: 10(-8.2,-2.77)
  oval 1.372x3.15 hole 0.61x2.388: 11(-9.9,-1.59) 12(2.9,-1.59)
  oval 1.372x2.667 hole 0.61x1.905: 13(-11.4,-10.35) 14(4.4,-10.35)
TOKO_FDUM0640J-H-R36M-P3_4P
  custom 0.686x0.686 smd: 1(0,0) 4(8.509,0)
  rect 2.362x0.508 smd: 2(1.448,0) 3(7.061,0)
TP0610K-T1-E3_SOT23-3
  oval 1.016x1.524 smd: 1(0,0) 2(0.965,2.083) 3(-0.965,2.083)
TPC12
  round 0.305 smd: 1(0,0)
TPS2543RTER_QFN16_3X3
  oval 0.254x1.016 smd: 1(0,0) 2(0.5,0) 3(1,0) 4(1.5,0) 9(1.5,2.975) 10(1,2.975) 11(0.5,2.975) 12(0,2.975)
  oval 1.016x0.254 smd: 5(2.238,0.738) 6(2.238,1.238) 7(2.238,1.738) 8(2.238,2.238) 13(-0.738,2.238) 14(-0.738,1.738) 15(-0.738,1.238) 16(-0.738,0.738)
  rect 1.702x1.702 smd: 17(0.75,1.488)
TPS22965DSGR_SON8_2X2
  oval 0.254x0.787 smd: 1(0,0) 2(0.5,0) 3(1,0) 4(1.5,0) 5(1.5,2.2) 6(1,2.2) 7(0.5,2.2) 8(0,2.2)
  rect 1.6x0.889 smd: 9(0.75,1.1)
TPS22966DPUR_SON14_2X3
  oval 0.203x0.762 smd: 1(0,0) 2(0.4,0) 3(0.8,0) 4(1.2,0) 5(1.6,0) 6(2,0) 7(2.4,0) 8(2.4,2.05) 9(2,2.05) 10(1.6,2.05) 11(1.2,2.05) 12(0.8,2.05) 13(0.4,2.05) 14(0,2.05)
  rect 2.489x0.889 smd: 15(1.2,1.025)
TPS51362RVER_QFN28_4P5X3P5
  oval 0.203x1.041 smd: 1(0,0) 2(0.4,0) 3(0.8,0) 4(1.2,0) 5(1.6,0) 6(2,0) 7(2.4,0) 8(2.8,0) 9(3.2,0) 15(3.2,3.45) 16(2.8,3.45) 17(2.4,3.45) 18(2,3.45) 19(1.6,3.45) 20(1.2,3.45) 21(0.8,3.45) 22(0.4,3.45) 23(0,3.45)
  oval 1.041x0.203 smd: 10(3.825,0.925) 11(3.825,1.325) 12(3.825,1.725) 13(3.825,2.125) 14(3.825,2.525) 24(-0.625,2.525) 25(-0.625,2.125) 26(-0.625,1.725) 27(-0.625,1.325) 28(-0.625,0.925)
  rect 3.099x2.108 smd: 29(1.6,1.725)
TPS51622RSM_QFN32_4X4
  oval 0.203x0.914 smd: 1(0,0) 2(0.4,0) 3(0.8,0) 4(1.2,0) 5(1.6,0) 6(2,0) 7(2.4,0) 8(2.8,0) 17(2.8,4.077) 18(2.4,4.077) 19(2,4.077) 20(1.6,4.077) 21(1.2,4.077) 22(0.8,4.077) 23(0.4,4.077) 24(0,4.077)
  oval 0.914x0.203 smd: 9(3.438,0.639) 10(3.438,1.039) 11(3.438,1.438) 12(3.438,1.838) 13(3.438,2.239) 14(3.438,2.639) 15(3.438,3.039) 16(3.438,3.438) 25(-0.639,3.438) 26(-0.639,3.039) 27(-0.639,2.639) 28(-0.639,2.239) 29(-0.639,1.838) 30(-0.639,1.438) 31(-0.639,1.039) 32(-0.639,0.639)
  rect 2.794x2.794 smd: 33(1.4,2.039)
TPS62130RGTR_QFN16_3X3
  oval 0.254x1.016 smd: 1(0,0) 2(0.5,0) 3(1,0) 4(1.5,0) 9(1.5,2.975) 10(1,2.975) 11(0.5,2.975) 12(0,2.975)
  oval 1.016x0.254 smd: 5(2.238,0.738) 6(2.238,1.238) 7(2.238,1.738) 8(2.238,2.238) 13(-0.738,2.238) 14(-0.738,1.738) 15(-0.738,1.238) 16(-0.738,0.738)
  rect 1.702x1.702 smd: 17(0.75,1.488)
TPS62140RGTR_QFN16_3X3
  oval 0.254x1.016 smd: 1(0,0) 2(0.5,0) 3(1,0) 4(1.5,0) 9(1.5,2.975) 10(1,2.975) 11(0.5,2.975) 12(0,2.975)
  oval 1.016x0.254 smd: 5(2.238,0.738) 6(2.238,1.238) 7(2.238,1.738) 8(2.238,2.238) 13(-0.738,2.238) 14(-0.738,1.738) 15(-0.738,1.238) 16(-0.738,0.738)
  rect 1.702x1.702 smd: 17(0.75,1.488)
TPS62150RGTR_QFN16_3X3
  oval 0.254x1.016 smd: 1(0,0) 2(0.5,0) 3(1,0) 4(1.5,0) 9(1.5,2.975) 10(1,2.975) 11(0.5,2.975) 12(0,2.975)
  oval 1.016x0.254 smd: 5(2.238,0.738) 6(2.238,1.238) 7(2.238,1.738) 8(2.238,2.238) 13(-0.738,2.238) 14(-0.738,1.738) 15(-0.738,1.238) 16(-0.738,0.738)
  rect 1.702x1.702 smd: 17(0.75,1.488)
TXB0104PWR_TSSOP14
  oval 0.381x1.651 smd: 1(0,0) 2(0.65,0) 3(1.3,0) 4(1.95,0) 5(2.6,0) 6(3.25,0) 7(3.9,0) 8(3.9,5.775) 9(3.25,5.775) 10(2.6,5.775) 11(1.95,5.775) 12(1.3,5.775) 13(0.65,5.775) 14(0,5.775)
TXS0102YZPR_DSBGA_8P
  round 0.254 smd: A1(0,0) A2(0.5,0) B1(0,-0.5) B2(0.5,-0.5) C1(0,-1) C2(0.5,-1) D1(0,-1.5) D2(0.5,-1.5)
TYCO_2041119-1_52P
  round 1.6 hole 1.6 unplated: (-0.7,4.1)
  round 1.092 hole 1.092 unplated: (24.3,4.1)
  oval 0.61x2.007 smd: 1(0,0) 2(0.4,8.2) 3(0.8,0) 4(1.2,8.2) 5(1.6,0) 6(2,8.2) 7(2.4,0) 8(2.8,8.2) 9(3.2,0) 10(3.6,8.2) 11(4,0) 12(4.4,8.2) 13(4.8,0) 14(5.2,8.2) 15(5.6,0) 16(6,8.2) 17(9.6,0) 18(10,8.2) 19(10.4,0) 20(10.8,8.2) 21(11.2,0) 22(11.6,8.2) 23(12,0) 24(12.4,8.2) 25(12.8,0) 26(13.2,8.2) 27(13.6,0) 28(14,8.2) 29(14.4,0) 30(14.8,8.2) 31(15.2,0) 32(15.6,8.2) 33(16,0) 34(16.4,8.2) 35(16.8,0) 36(17.2,8.2) 37(17.6,0) 38(18,8.2) 39(18.4,0) 40(18.8,8.2) 41(19.2,0) 42(19.6,8.2) 43(20,0) 44(20.4,8.2) 45(20.8,0) 46(21.2,8.2) 47(21.6,0) 48(22,8.2) 49(22.4,0) 50(22.8,8.2) 51(23.2,0) 52(23.6,8.2)
  rect 2.311x3.2 smd: 53(-2.85,0.6) 54(26.45,0.6)
W25Q64FVSSIQ_SO8
  oval 0.635x1.676 smd: 1(0,0) 2(1.27,0) 3(2.54,0) 4(3.81,0) 5(3.81,7.25) 6(2.54,7.25) 7(1.27,7.25) 8(0,7.25)
Y_7A08000006_2P
  rect 1.702x2.388 smd: 1(0,0) 2(3.7,0)
Y_CM31532768DZFT_2P
  rect 1.092x1.905 smd: 1(0,0) 2(2.5,0)
Y_Q13FC1350000200_2P
  rect 0.991x1.803 smd: 1(0,0) 2(2.5,0)
Y_X3G024000DC1H_4P
  rect 1.397x1.194 smd: 1(0,0) 2(2.2,0) 3(2.2,1.7) 4(0,1.7)

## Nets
1.2V_DDR_PWROK: PU601.10 R1133.1
1.05V_VREF: PC501.1 PU501.26
1.05VA_PG: PU501.1 R931.1
1.05VS_PG: D109.1 R1353.2 RH438.2 U672.2 U697.1
1.05VS_PG_EC: R1353.1 U34.A1
1.5VS_PWROK: PU401.4 R982.1
1.05VS_VCCST_PG: R1132.2 R1180.1 RC150.1 U672.4
1.5VSP_FB: PC404.2 PR407.2 PR408.1 PU401.5
1.8VS_PWROK: PU402.4 R934.1
3VALW_PG: PR348.2 PU305.4
5VA_EN: PD307.2 RH309.1 U34.B2
5VS_EN: R1027.1 R1146.2 U717.3
+0.6VSP: PC606.1 PC607.1 PJP603.1 PU601.2 PU601.20
+0.675VS: CD93.1 CD94.1 CD95.1 CD96.1 CD97.1 CD98.1 CD101.1 CD102.1 CD103.1 CD104.1 CD105.1 CD106.1 CD107.1 CD110.1 MC1267.1 MC1268.1 PJP603.2 RD25.2 RD26.2 RD27.2 RD28.2 RD29.2 RD30.2 RD31.2 RD32.2 RD33.2 RD34.2 RD35.2 RD36.2 RD37.2 RD38.2 RD39.2 RD40.2 RD41.2 RD42.2 RD43.2 RD44.2 RD45.2 RD46.2 RD47.2 RD48.2 RD49.2 RD50.2 RD51.2 RD52.2 RD53.2 RD54.2 RD55.2 RD56.2 RD57.2 RD58.2 RD59.2 RD60.2 RD61.2 RD62.2 RD63.2 RD64.2 RD65.2 RD66.2 RD67.2 RD68.2 RD69.2 RD70.2 RD71.2 RD72.2 RD75.2 RD76.2 RD77.2 RD78.2 RD87.2 RD88.2 RD89.2 RD90.2
+1.2V_B+: PC602.1 PC603.1 PC604.1 PL601.2 PQ601.5 PR611.1
+1.2V_FB: PC614.1 PR608.1 PR610.1 PU601.6
+1.2V_TON: PR611.2 PU601.9
+1.2VP: PC610.1 PC611.1 PC614.2 PC615.1 PJP602.1 PL602.1 PR608.2 PU601.5
+1.2VS_DVDD: CA1.1 CA2.1 CA3.1 CA4.1 CA5.1 CA6.1 CA18.1 CA19.1 CA20.1 LA1.1 UA1.1 UA1.15 UA1.25 UA1.37
+1.05VA: C1228.1 C1243.1 CH1214.1 CH1239.1 PJP501.1 Q360.5 R1355.1 RH38.1 RH39.1 RH40.1 RH375.1 RH405.1 RH406.2 RH445.1 U673.4 U673.5 U673.9 U673.10 U673.11 U673.12 U673.13 U673.14 U673.18 U673.19
+1.05VDX_MODPHY: C1209.1 LH10.1 LH11.1 Q360.1 Q360.2 Q360.3 R300.1 R1240.1
+1.05VDX_MODPHY_D: Q39.1 R300.2
+1.05VS: C1240.1 C1244.2 CH1.1 CH39.1 CH1215.1 CH1216.1 CH1217.1 CH1222.1 CH1223.1 CH1233.1 CH1234.1 CH1235.1 LH12.1 R297.1 R1190.2 R1355.2 RH51.1 RH340.1 RH355.1 RH356.1 U673.6 U673.7 U673.8 UCPU1.AE8 UCPU1.AE9 UCPU1.AF9 UCPU1.AF22 UCPU1.AG8 UCPU1.AG13 UCPU1.AG14 UCPU1.AG16 UCPU1.AG17 UCPU1.H11 UCPU1.H15 UCPU1.J11 UCPU1.J17 UCPU1.N8 UCPU1.P9 UCPU1.R21 UCPU1.T21
+1.5VS: PJP402.2 R296.1 R1305.1 UCPU1.J15
+1.5VS_3.3VS_AUDIO: C1279.1 CA22.1 CH85.1 JIOL1.4 Q351.1 RH42.1 U717.8 U717.9 UA1.9 UA2.5 UA3.5 UCPU1.AH14
+1.05VS_B+: PC510.1 PC511.1 PC512.1 PC513.1 PL501.2 PU501.15 PU501.16 PU501.17
+1.5VS_D: Q34.1 R296.2
+1.5VS_FSW: PR411.1 PU401.7
+1.05VS_VCCST: CH1204.1 CH1205.1 PC721.1 PR735.1 PR736.1 PR737.1 R1132.1 R1179.1 R1211.1 RC43.2 RC45.2 RC46.2 RC48.2 RC93.2 RC95.1 RC149.2 RH340.2 UCPU1.AC22 UCPU1.AE22 UCPU1.AE23
+1.05VS_XDP: JXDP.43 JXDP.44 RH51.2
+1.5VSP: PC404.1 PC405.1 PJP402.1 PL401.2 PR407.1 PR411.2 PU401.14
+1.05VSP: PC505.1 PC506.1 PC507.1 PC508.1 PJP501.2 PL502.2 PU501.22
+1.5VSP_LX: PL401.1 PR406.1 PU401.1 PU401.2 PU401.3
+1.5VSP_VIN: PC403.1 PJP401.2 PU401.10 PU401.11 PU401.12
+1.8VP: PC412.1 PC413.1 PC414.1 PJP404.1 PL402.2 PR419.1 PR424.2 PU402.14
+1.8VS: C1284.1 C1286.1 C1288.1 PJP404.2 R1131.2 R1188.2 R1204.2 R1327.1 R1328.1 R1360.1 R1361.1 R1362.1 R1363.1 R1364.1 R1365.1 R1368.1 R1369.1 R1370.1 R1371.1 RH350.2 U671.1 U677.1 U679.C1
+1.8VSP_LX: PL402.1 PR418.1 PU402.1 PU402.2 PU402.3
+1.35V_DDR: CC160.1 CC161.1 CC162.1 CC163.1 CC164.1 CC165.1 CC233.1 CC234.1 CC238.1 CC239.1 CC240.1 CD14.1 CD15.1 CD16.1 CD17.1 CD18.1 CD19.1 CD20.1 CD21.1 CD22.1 CD37.1 CD38.1 CD39.1 CD40.1 CD41.1 CD42.1 CD43.1 CD44.1 CD58.1 CD59.1 CD60.1 CD61.1 CD62.1 CD63.1 CD64.1 CD65.1 CD66.1 CD81.1 CD82.1 CD83.1 CD84.1 CD85.1 CD86.1 CD87.1 CD88.1 CD111.1 CD112.1 CD113.1 CD114.1 CD115.1 CD116.1 CD117.1 CD118.1 CD119.1 CD120.1 CD121.1 CD122.1 CD123.1 CD124.1 CD125.1 CD126.1 PJP602.2 PJP604.2 RC75.1 RD13.1 RD17.1 RD18.1 RD73.2 RD74.2 UC1.5 UCPU1.AH26 UCPU1.AJ31 UCPU1.AJ33 UCPU1.AJ37 UCPU1.AN33 UCPU1.AP43 UCPU1.AR48 UCPU1.AY35 UCPU1.AY40 UCPU1.AY44 UCPU1.AY50 UD1.A1 UD1.A8 UD1.B2 UD1.C1 UD1.C9 UD1.D2 UD1.D9 UD1.E9 UD1.F1 UD1.G7 UD1.H2 UD1.H9 UD1.K2 UD1.K8 UD1.N1 UD1.N9 UD1.R1 UD1.R9 UD2.A1 UD2.A8 UD2.B2 UD2.C1 UD2.C9 UD2.D2 UD2.D9 UD2.E9 UD2.F1 UD2.G7 UD2.H2 UD2.H9 UD2.K2 UD2.K8 UD2.N1 UD2.N9 UD2.R1 UD2.R9 UD4.A1 UD4.A8 UD4.B2 UD4.C1 UD4.C9 UD4.D2 UD4.D9 UD4.E9 UD4.F1 UD4.G7 UD4.H2 UD4.H9 UD4.K2 UD4.K8 UD4.N1 UD4.N9 UD4.R1 UD4.R9 UD5.A1 UD5.A8 UD5.B2 UD5.C1 UD5.C9 UD5.D2 UD5.D9 UD5.E9 UD5.F1 UD5.G7 UD5.H2 UD5.H9 UD5.K2 UD5.K8 UD5.N1 UD5.N9 UD5.R1 UD5.R9 UD6.A1 UD6.A8 UD6.B2 UD6.C1 UD6.C9 UD6.D2 UD6.D9 UD6.E9 UD6.F1 UD6.G7 UD6.H2 UD6.H9 UD6.K2 UD6.K8 UD6.N1 UD6.N9 UD6.R1 UD6.R9 UD7.A1 UD7.A8 UD7.B2 UD7.C1 UD7.C9 UD7.D2 UD7.D9 UD7.E9 UD7.F1 UD7.G7 UD7.H2 UD7.H9 UD7.K2 UD7.K8 UD7.N1 UD7.N9 UD7.R1 UD7.R9 UD9.A1 UD9.A8 UD9.B2 UD9.C1 UD9.C9 UD9.D2 UD9.D9 UD9.E9 UD9.F1 UD9.G7 UD9.H2 UD9.H9 UD9.K2 UD9.K8 UD9.N1 UD9.N9 UD9.R1 UD9.R9 UD10.A1 UD10.A8 UD10.B2 UD10.C1 UD10.C9 UD10.D2 UD10.D9 UD10.E9 UD10.F1 UD10.G7 UD10.H2 UD10.H9 UD10.K2 UD10.K8 UD10.N1 UD10.N9 UD10.R1 UD10.R9
+3.3VDX_SSD: C719.1 C720.1 C721.1 C722.1 JSATA1.2 JSATA1.24 JSATA1.39 JSATA1.41 JSATA1.52 PJP308.1 R1366.1
+3.3VDX_SSD_LX: PL307.1 PR334.1 PU304.1 PU304.2 PU304.3
+3.3VDX_SSD_VIN: PC326.1 PC327.1 PL308.2 PU304.10 PU304.11 PU304.12
+3.3VDX_SSDP: PC328.1 PC329.1 PC330.1 PJP308.2 PL307.2 PR335.1 PR336.2 PU304.14
+3V_BATMAN: C1294.1 R1346.2 R1347.2 R1348.1 R1349.1 U714.11
+3V_D: Q5.1 R298.2
+3V_NFC: C1134.1 JNFC1.2 JNFC1.3 JNFC1.15 R973.1 R1242.2
+3V_PCH: C352.1 C1261.1 C1262.1 CH1220.1 CH1236.1 JAPS.12 JAPS.18 R298.1 R811.1 R1239.1 R1242.1 R1285.1 R1312.2 R1324.1 R1326.2 RH70.2 RH72.2 RH154.2 RH188.2 RH270.2 RH271.2 RH274.1 RH294.2 RH295.2 RH303.2 RH341.1 RH351.1 RH383.2 RH398.1 RH400.2 RH415.2 RH416.2 RH426.2 RP7.5 RP7.6 RP7.7 RP7.8 RP11.5 RP11.6 RP11.7 RP11.8 RP19.6 RP19.7 U663.16 U672.5 U690.5 U691.5 U697.5 UCPU1.AA9 UCPU1.AC9 UCPU1.AE20 UCPU1.AE21
+3V_PCH_DSW: CH1224.1 RH12.2 RH146.2 RH348.2 RH351.2 RH402.2 RP20.5 RP20.6 UCPU1.AH10
+3VALW: C617.1 C1100.2 C1199.1 C1219.1 C1259.1 C1260.1 C1289.1 JAPS.16 JIOL1.7 JLVDS2.17 PJP310.1 PR102.2 PR107.2 PR113.2 PR126.1 PR224.2 PR308.1 PR318.1 PR328.1 PR338.1 PR348.1 PU307.5 Q316.2 Q316.5 Q318.2 Q318.5 Q320.2 R216.1 R977.2 R1281.1 R1282.1 RH348.1 U636.C6 U687.5 U688.3 U688.5 U689.5 U699.5 U710.5 U713.5 U716.1 U716.2 U716.6 U716.7 U718.1 U718.2 U718.6 U718.7 U719.1 U719.2 U719.4 U719.6 U719.7 U722.1 U722.2
+3VALW_EC: C276.1 C277.1 C278.1 C279.1 C280.2 C281.2 L43.1 PR117.2 R216.2 R219.2 R221.2 R229.2 R230.2 R241.2 R604.1 R811.2 R922.2 R927.1 R980.2 R990.2 R1156.1 R1297.2 R1354.2 R1386.2 RP16.7 RP16.8 RP21.5 RP21.6 RP22.5 RP22.7 U34.J4 U34.J7 U34.K7 U34.K12 U34.M12
+3VALW_LX: PL309.1 PR344.1 PU305.1 PU305.2 PU305.3
+3VALW_VIN: PC334.1 PC335.1 PL310.2 PU305.10 PU305.11 PU305.12
+3VALWP: PC336.1 PC337.1 PC338.1 PJP310.2 PL309.2 PR345.1 PR346.2 PU305.14
+3VDX: PJP306.1 U664.1 U664.2 U721.5
+3VDX_LX: PL305.1 PR324.1 PU303.1 PU303.2 PU303.3
+3VDX_VIN: PC318.1 PC319.1 PL306.2 PU303.10 PU303.11 PU303.12
+3VDXP: PC320.1 PC321.1 PC322.1 PJP306.2 PL305.2 PR325.1 PR326.2 PU303.14
+3VLP: PC341.1 PU306.3 R921.2 R939.1 R1349.2 RP16.5 RP16.6 RP22.6 RTCD1.3 U712.5
+3VNS_PWR: C965.1 C966.1 C969.1 C970.1 C976.1 C977.1 C978.1 C979.1 C1148.1 C1149.1 JSATA1.22 JSNRDG.1 Q352.2 Q352.5 R854.2 R855.2 R1003.2 R1091.1 R1092.2 R1143.2 R1175.1 R1176.1 R1205.2 R1220.2 R1227.2 R1251.2 R1319.2 RH461.2 RH462.2 RP12.1 RP12.2 RP12.3 RP12.4 U636.A1 U636.A8 U636.F7 U636.G6 U636.G8 U636.H1 U637.1 U637.14 U638.1 U638.15 U638.16 U653.1 U653.7 U653.14 U653.15
+3VS: C655.1 C1256.1 C1283.1 C1285.1 C1287.1 CD23.1 CD67.1 CH6.1 CH47.1 CH1225.1 CH1226.1 D113.2 JDEBUG.9 JLVDS2.10 MC1276.1 MC1277.1 MD50.5 PR723.2 PR725.1 PR746.1 PU701.21 Q326.2 Q344.2 Q359.2 Q359.5 QH3.2 QH3.5 QH4.2 QH4.5 R884.2 R930.1 R1033.2 R1103.2 R1163.2 R1182.2 R1185.2 R1289.1 R1306.1 R1311.2 R1393.1 RC159.1 RD10.1 RH29.2 RH35.1 RH37.1 RH54.1 RH56.1 RH91.1 RH95.1 RH98.1 RH99.1 RH100.1 RH103.1 RH107.1 RH110.1 RH180.2 RH196.2 RH248.1 RH281.1 RH282.1 RH302.2 RH354.2 RH367.2 RH380.1 RH381.1 RH384.2 RH390.2 RH391.2 RH392.2 RH395.1 RH396.1 RH397.1 RH424.2 RH425.2 RH440.2 RH441.2 RH452.1 RH457.2 RH458.2 RH459.2 RH460.2 RH465.2 RP2.1 RP2.2 RP2.3 RP2.4 RP15.1 RP15.2 RP15.3 RP15.4 RP19.5 RP20.8 RV2.2 U48.8 U635.5 U671.14 U675.5 U677.14 U679.B2 U682.5 U709.5 U716.13 U716.14 UCPU1.K14 UCPU1.K16 UCPU1.V8 UCPU1.W9 UCPU1.Y8 UD3.7 UD3.8 UD8.7 UD8.8 UH5.5
+3VS_AUDIO: C1101.2 CA7.1 CA8.1 CA9.1 CA10.1 CA11.1 CA12.1 JIOL1.6 R1261.1 R1265.1 R1266.1 R1318.2 UA1.14 UA1.16 UA1.42
+3VS_CAM: C1158.1 C1159.1 JLVDS2.4 R1128.2
+3VS_NGFF: C712.1 C713.1 C715.1 C716.1 C1215.1 JNGFF1.2 JNGFF1.4 JNGFF1.64 JNGFF1.66 Q346.2 R942.1 R1137.1 R1197.1 R1226.2
+3VS_TOUCH: C1200.1 C1225.1 JLVDS1.17 JTP1.1 MD90.5 Q363.2 Q364.2 R1299.1 R1320.2 R1385.1 RH364.2 RH365.2
+3VS_TPM: C1135.1 C1136.1 C1137.1 C1138.1 C1139.1 C1140.1 C1298.1 R975.2 R1392.2 R1393.2 U652.5 U652.10 U652.19 U652.24 U698.5
+5V_USB_P0: C1109.1 C1110.1 JUSB2.1 MD82.8 US2.6 US2.7 US2.8
+5V_USB_P1: C265.1 C303.1 JUSB1.1 MD74.8 US1.12
+5VA: C1098.2 C1161.1 C1203.1 C1213.1 C1241.1 C1254.1 C1299.1 JIOL1.5 PC504.1 PC608.1 PJP302.2 PR104.2 PR505.1 PR606.1 PR731.2 PU501.18 PU601.12 Q354.3 Q355.3 Q356.3 Q357.3 Q358.3 R920.2 R1341.2 RP14.1 RP14.2 RP14.3 RP14.4 U664.4 U664.6 U664.7 U673.2 U676.5 U716.4 U717.1 U717.2 U717.4 U718.4 U722.4
+5VDX_LX: PL303.1 PR314.1 PU302.1 PU302.2 PU302.3
+5VDX_VIN: PC310.1 PC311.1 PL304.2 PU302.10 PU302.11 PU302.12
+5VDX_WALKPORT: C962.1 C963.1 C1172.1 C1173.1 PJP304.2 R1165.2 R1167.2 R1213.2 US1.1 US2.2 US2.3
+5VDXP: PC312.1 PC313.1 PC314.1 PJP304.1 PL303.2 PR315.1 PR316.2 PU302.14
+5VS: C1102.2 C1153.1 C1162.1 CV13.1 F1.2 JFAN1.4 PC713.1 PC723.1 PR720.2 PR738.2 PU702.2 PU703.2 Q329.3 QC5.2 QV2.2 R886.2 R989.2 U717.13 U717.14 UV1.16
+5VS_AUDIO: C1099.2 C1146.2 JIOL1.1 JIOL1.2 JIOL1.3 R1125.2
+5VS_KBL: C1059.1 F1.1 JBL1.4
+V1.05A_AOSCSUS: CH1232.1 CH1240.1 L63.1 UCPU1.AB8
+V1.05A_AOSCSUS_L: L63.2 RH406.1
+V1.05A_DCPSUS: RH405.2 UCPU1.AD8 UCPU1.AD10 UCPU1.AH13 UCPU1.J13
+V1.05S_APLLOPI: CH1212.1 CH1213.1 LH12.2 UCPU1.AA21 UCPU1.W21
+V1.05S_ASATA3PLL: CH1210.1 CH1211.1 LH11.2 RH43.2 UCPU1.A12 UCPU1.B11
+V1.05S_AUSB3PLL: CH1208.1 CH1209.1 LH10.2 RH338.1 UCPU1.B18 UCPU1.B27
+V1.05S_AXCK_DCB: CH1228.1 CH1229.1 L61.2 UCPU1.J18 UCPU1.K19
+V1.05S_AXCK_DCB_L: L61.1 RH355.2
+V1.05S_AXCK_LCPLL: CH1230.1 CH1231.1 L62.2 RH113.2 UCPU1.A20
+V1.05S_AXCK_LCPLL_L: L62.1 RH356.2
+V1.05VS_VCCHSIO: CH40.1 CH41.1 R1240.2 UCPU1.K9 UCPU1.L10 UCPU1.M9
+V5A_LX: PL301.1 PR304.1 PU301.1 PU301.2 PU301.3
+V5A_VIN: PC302.1 PC303.1 PL302.2 PU301.10 PU301.11 PU301.12
+V5AP: PC304.1 PC305.1 PC306.1 PJP302.1 PL301.2 PR305.1 PR306.2 PU301.14
+V18R: C293.1 U34.L1
+VCC_CORE: MC1269.1 MC1270.1 MC1271.1 MC1272.1 PC801.1 PC802.1 PC803.1 PC804.1 PC805.1 PC806.1 PC807.1 PC808.1 PC809.1 PC810.1 PC811.1 PC812.1 PC813.1 PC814.1 PC815.1 PC816.1 PC817.1 PC818.1 PC819.1 PC820.1 PC821.1 PC822.1 PC823.1 PC824.1 PC825.1 PC826.1 PC827.1 PC828.1 PC829.1 PC830.1 PL701.4 PL702.4 RC97.1 UCPU1.AB57 UCPU1.AD57 UCPU1.AG57 UCPU1.C24 UCPU1.C28 UCPU1.C32 UCPU1.C36 UCPU1.C40 UCPU1.C44 UCPU1.C48 UCPU1.C52 UCPU1.C56 UCPU1.E23 UCPU1.E25 UCPU1.E27 UCPU1.E29 UCPU1.E31 UCPU1.E33 UCPU1.E35 UCPU1.E37 UCPU1.E39 UCPU1.E41 UCPU1.E43 UCPU1.E45 UCPU1.E47 UCPU1.E49 UCPU1.E51 UCPU1.E53 UCPU1.E55 UCPU1.E57 UCPU1.F24 UCPU1.F28 UCPU1.F32 UCPU1.F36 UCPU1.F40 UCPU1.F44 UCPU1.F48 UCPU1.F52 UCPU1.F56 UCPU1.F59 UCPU1.G23 UCPU1.G25 UCPU1.G27 UCPU1.G29 UCPU1.G31 UCPU1.G33 UCPU1.G35 UCPU1.G37 UCPU1.G39 UCPU1.G41 UCPU1.G43 UCPU1.G45 UCPU1.G47 UCPU1.G49 UCPU1.G51 UCPU1.G53 UCPU1.G55 UCPU1.G57 UCPU1.H23 UCPU1.J23 UCPU1.K23 UCPU1.K57 UCPU1.L22 UCPU1.M23 UCPU1.M57 UCPU1.P57 UCPU1.U57 UCPU1.W57
+VCCIO_OUT: CH1241.1 UCPU1.A59
+VCCIOA_OUT: RC36.2 UCPU1.E20
+VCCP_D: Q4.1 R297.2
DVDD-12-SWR: LA1.2 UA1.13
DVDD_25: CA13.1 CA14.1 CA21.1 R1186.1 UA1.43
